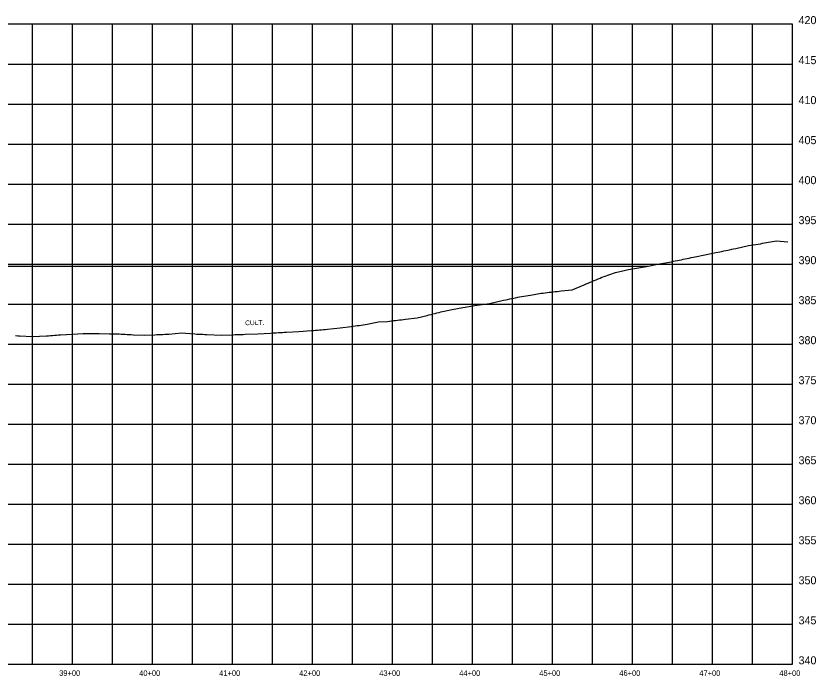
# Model space of a CAD drawing. Extents: x 1189978 to 1314812, y 571533 to 629339.
# Drawn here: x 1230434 to 1231434, y 623630 to 624455 of the extents above; entities that cross this region are included whole.
import ezdxf

# ---------------------------------------------------------------- set-up
doc = ezdxf.new("R2010")
doc.units = 0
for name, color, linetype in [('DESIGN - SHEET - Corner Text', 7, 'Continuous'), ('DESIGN - SHEET - Light Grid', 7, 'Continuous'), ('SURVEY - DRAINAGE - Pipes and Culverts Text', 7, 'Continuous'), ('SURVEY - PROFILE - Drainage - Bridge Hydraulic Data with Text', 7, 'Continuous')]:
    doc.layers.add(name, color=color, linetype=linetype)

msp = doc.modelspace()

# ---------------------------------------------------------------- linework, layer by layer
at = {"layer": 'DESIGN - SHEET - Light Grid'}
for p, q in [((1231404.88, 624444.99), (1227604.88, 624444.99)), ((1230454.88, 623644.99), (1230454.88, 624444.99)), ((1230504.88, 623644.99), (1230504.88, 624444.99)), ((1230554.88, 623644.99), (1230554.88, 624444.99)), ((1230604.88, 623644.99), (1230604.88, 624444.99)), ((1230654.88, 623644.99), (1230654.88, 624444.99)), ((1230704.88, 623644.99), (1230704.88, 624444.99)), ((1230754.88, 623644.99), (1230754.88, 624444.99)), ((1230804.88, 623644.99), (1230804.88, 624444.99)), ((1230854.88, 623644.99), (1230854.88, 624444.99)), ((1230904.88, 623644.99), (1230904.88, 624444.99)), ((1230954.88, 623644.99), (1230954.88, 624444.99)), ((1231004.88, 623644.99), (1231004.88, 624444.99)), ((1231054.88, 623644.99), (1231054.88, 624444.99)), ((1231104.88, 623644.99), (1231104.88, 624444.99)), ((1231154.88, 623644.99), (1231154.88, 624444.99)), ((1231204.88, 623644.99), (1231204.88, 624444.99)), ((1231254.88, 623644.99), (1231254.88, 624444.99)), ((1231304.88, 623644.99), (1231304.88, 624444.99)), ((1231354.88, 623644.99), (1231354.88, 624444.99)), ((1231404.88, 623644.99), (1231404.88, 624444.99)), ((1227604.88, 624394.99), (1231404.88, 624394.99)), ((1227604.88, 624344.99), (1231404.88, 624344.99)), ((1227604.88, 624294.99), (1231404.88, 624294.99)), ((1227604.88, 624244.99), (1231404.88, 624244.99)), ((1227604.88, 624194.99), (1231404.88, 624194.99)), ((1227604.88, 624144.99), (1231404.88, 624144.99)), ((1227604.88, 624094.99), (1231404.88, 624094.99)), ((1227604.88, 624044.99), (1231404.88, 624044.99)), ((1227604.88, 623994.99), (1231404.88, 623994.99)), ((1227604.88, 623944.99), (1231404.88, 623944.99)), ((1227604.88, 623894.99), (1231404.88, 623894.99)), ((1227604.88, 623844.99), (1231404.88, 623844.99)), ((1227604.88, 623794.99), (1231404.88, 623794.99)), ((1227604.88, 623744.99), (1231404.88, 623744.99)), ((1227604.88, 623694.99), (1231404.88, 623694.99)), ((1227604.88, 623644.99), (1231398.82, 623644.99)), ((1227604.88, 623644.99), (1231404.88, 623644.99))]:
    msp.add_line(p, q, dxfattribs=at)
at = {"layer": 'SURVEY - DRAINAGE - Pipes and Culverts Text'}
msp.add_line((1227829.3, 624142.69), (1231224.2, 624142.69), dxfattribs=at)
at = {"layer": 'SURVEY - PROFILE - Drainage - Bridge Hydraulic Data with Text'}
msp.add_lwpolyline([(1230433.91, 624055.93), (1230436.56, 624055.62), (1230438.91, 624055.45), (1230454.87, 624054.73), (1230472.45, 624055.41), (1230475.17, 624055.58), (1230477.45, 624055.86), (1230480.17, 624056.03), (1230482.45, 624056.3), (1230485.16, 624056.47), (1230487.45, 624056.75), (1230490.15, 624056.92), (1230504.83, 624057.69), (1230518.25, 624058.41), (1230520.92, 624058.44), (1230523.25, 624058.42), (1230525.91, 624058.44), (1230528.25, 624058.42), (1230530.91, 624058.44), (1230533.24, 624058.42), (1230535.9, 624058.44), (1230538.24, 624058.42), (1230551.04, 624058.05), (1230563.21, 624057.79), (1230565.66, 624057.66), (1230568.2, 624057.53), (1230570.67, 624057.41), (1230573.2, 624057.27), (1230575.68, 624057.15), (1230578.19, 624057.01), (1230580.69, 624056.89), (1230595.04, 624056.18), (1230608.04, 624056.82), (1230610.4, 624056.93), (1230613.04, 624057.08), (1230615.38, 624057.2), (1230618.05, 624057.34), (1230620.36, 624057.46), (1230623.06, 624057.61), (1230625.34, 624057.72), (1230641.15, 624059.09), (1230658.02, 624057.82), (1230660.18, 624057.75), (1230663.02, 624057.58), (1230665.17, 624057.51), (1230668.02, 624057.35), (1230670.17, 624057.28), (1230673.02, 624057.12), (1230690.57, 624056.12), (1230705.88, 624056.85), (1230708.2, 624056.93), (1230710.88, 624057.05), (1230713.26, 624057.13), (1230715.89, 624057.25), (1230718.33, 624057.33), (1230720.89, 624057.44), (1230736.78, 624057.88), (1230752.32, 624058.9), (1230754.71, 624059.05), (1230757.31, 624059.17), (1230759.72, 624059.33), (1230762.31, 624059.45), (1230764.72, 624059.61), (1230767.3, 624059.73), (1230769.72, 624059.88), (1230772.3, 624060.01), (1230787.65, 624060.85), (1230803.69, 624062.14), (1230806.01, 624062.33), (1230808.69, 624062.53), (1230810.99, 624062.72), (1230813.7, 624062.92), (1230815.97, 624063.11), (1230818.71, 624063.31), (1230820.95, 624063.5), (1230823.72, 624063.7), (1230839.64, 624065.47), (1230853.18, 624067.05), (1230855.95, 624067.51), (1230858.18, 624067.8), (1230860.91, 624068.26), (1230863.19, 624068.55), (1230865.86, 624069), (1230868.19, 624069.3), (1230870.82, 624069.74), (1230873.2, 624070.05), (1230887.26, 624073.11), (1230898.86, 624073.48), (1230901.36, 624073.82), (1230903.85, 624074.09), (1230906.33, 624074.43), (1230908.85, 624074.71), (1230911.31, 624075.04), (1230913.85, 624075.32), (1230916.28, 624075.65), (1230918.85, 624075.93), (1230921.26, 624076.25), (1230935.55, 624077.91), (1230948.08, 624081.03), (1230950.4, 624081.62), (1230953.08, 624082.25), (1230955.39, 624082.85), (1230958.08, 624083.48), (1230960.38, 624084.07), (1230963.08, 624084.71), (1230965.38, 624085.3), (1230979.48, 624088.27), (1230992.94, 624090.97), (1230995.58, 624091.48), (1230997.94, 624091.77), (1231000.56, 624092.27), (1231002.94, 624092.56), (1231005.55, 624093.06), (1231007.95, 624093.35), (1231010.54, 624093.84), (1231026.2, 624095.81), (1231043.73, 624099.92), (1231046.37, 624100.49), (1231048.72, 624100.99), (1231051.37, 624101.56), (1231053.71, 624102.06), (1231056.37, 624102.64), (1231058.69, 624103.14), (1231061.37, 624103.71), (1231063.68, 624104.21), (1231077.23, 624106.42), (1231090.63, 624108.72), (1231092.99, 624108.94), (1231095.63, 624109.3), (1231098.01, 624109.52), (1231100.63, 624109.88), (1231103.02, 624110.09), (1231105.63, 624110.45), (1231108.04, 624110.67), (1231110.63, 624111.02), (1231113.05, 624111.24), (1231115.63, 624111.59), (1231129.55, 624113.13), (1231144.32, 624119.24), (1231146.78, 624120.3), (1231149.31, 624121.33), (1231151.77, 624122.39), (1231154.31, 624123.42), (1231156.75, 624124.47), (1231159.3, 624125.51), (1231161.73, 624126.56), (1231164.29, 624127.6), (1231166.72, 624128.64), (1231169.29, 624129.69), (1231183.72, 624134.75), (1231199.81, 624138.49), (1231202.25, 624138.92), (1231204.8, 624139.33), (1231207.25, 624139.76), (1231209.8, 624140.17), (1231212.26, 624140.61), (1231214.79, 624141.01), (1231217.26, 624141.45), (1231219.78, 624141.86), (1231222.26, 624142.3), (1231238.55, 624145.62), (1231253.38, 624148.1), (1231255.89, 624148.6), (1231258.37, 624149.12), (1231260.88, 624149.62), (1231263.36, 624150.14), (1231265.88, 624150.64), (1231268.36, 624151.16), (1231270.87, 624151.65), (1231273.35, 624152.17), (1231275.86, 624152.67), (1231278.35, 624153.19), (1231280.86, 624153.69), (1231283.34, 624154.21), (1231295.13, 624156.87), (1231308.8, 624159.52), (1231311.3, 624160.01), (1231313.8, 624160.56), (1231316.29, 624161.05), (1231318.79, 624161.6), (1231321.28, 624162.09), (1231323.79, 624162.65), (1231326.27, 624163.13), (1231328.79, 624163.69), (1231331.26, 624164.18), (1231333.78, 624164.74), (1231349.92, 624168.42), (1231364.74, 624170.63), (1231367.26, 624171.22), (1231369.73, 624171.49), (1231372.25, 624172.07), (1231374.73, 624172.34), (1231377.23, 624172.92), (1231379.73, 624173.19), (1231382.22, 624173.78), (1231384.73, 624174.04), (1231398.82, 624173.02)], dxfattribs=at)

# ---------------------------------------------------------------- texts
at = {"layer": 'DESIGN - SHEET - Corner Text'}
for s, height, p in [('420', 10, (1231412.38, 624444.99)), ('415', 10, (1231412.38, 624394.99)), ('410', 10, (1231412.38, 624344.99)), ('405', 10, (1231412.38, 624294.99)), ('400', 10, (1231412.38, 624244.99)), ('395', 10, (1231412.38, 624194.99)), ('390', 10, (1231412.38, 624144.99)), ('385', 10, (1231412.38, 624094.99)), ('380', 10, (1231412.38, 624044.99)), ('375', 10, (1231412.38, 623994.99)), ('370', 10, (1231412.38, 623944.99)), ('365', 10, (1231412.38, 623894.99)), ('360', 10, (1231412.38, 623844.99)), ('355', 10, (1231412.38, 623794.99)), ('350', 10, (1231412.38, 623744.99)), ('345', 10, (1231412.38, 623694.99)), ('340', 10, (1231412.38, 623644.99)), ('39+00', 7, (1230488.33, 623630.49)), ('40+00', 7, (1230588.33, 623630.49)), ('41+00', 7, (1230688.33, 623630.49)), ('42+00', 7, (1230788.33, 623630.49)), ('43+00', 7, (1230888.33, 623630.49)), ('44+00', 7, (1230988.33, 623630.49)), ('45+00', 7, (1231088.33, 623630.49)), ('46+00', 7, (1231188.33, 623630.49)), ('47+00', 7, (1231288.33, 623630.49)), ('48+00', 7, (1231388.33, 623630.49))]:
    msp.add_text(s, height=height, dxfattribs=at).set_placement(p)
at = {"layer": 'SURVEY - DRAINAGE - Pipes and Culverts Text'}
msp.add_text('CULT.', height=6, rotation=1.38858, dxfattribs=at).set_placement((1230720.78, 624068.65))

doc.saveas('drawing.dxf')
